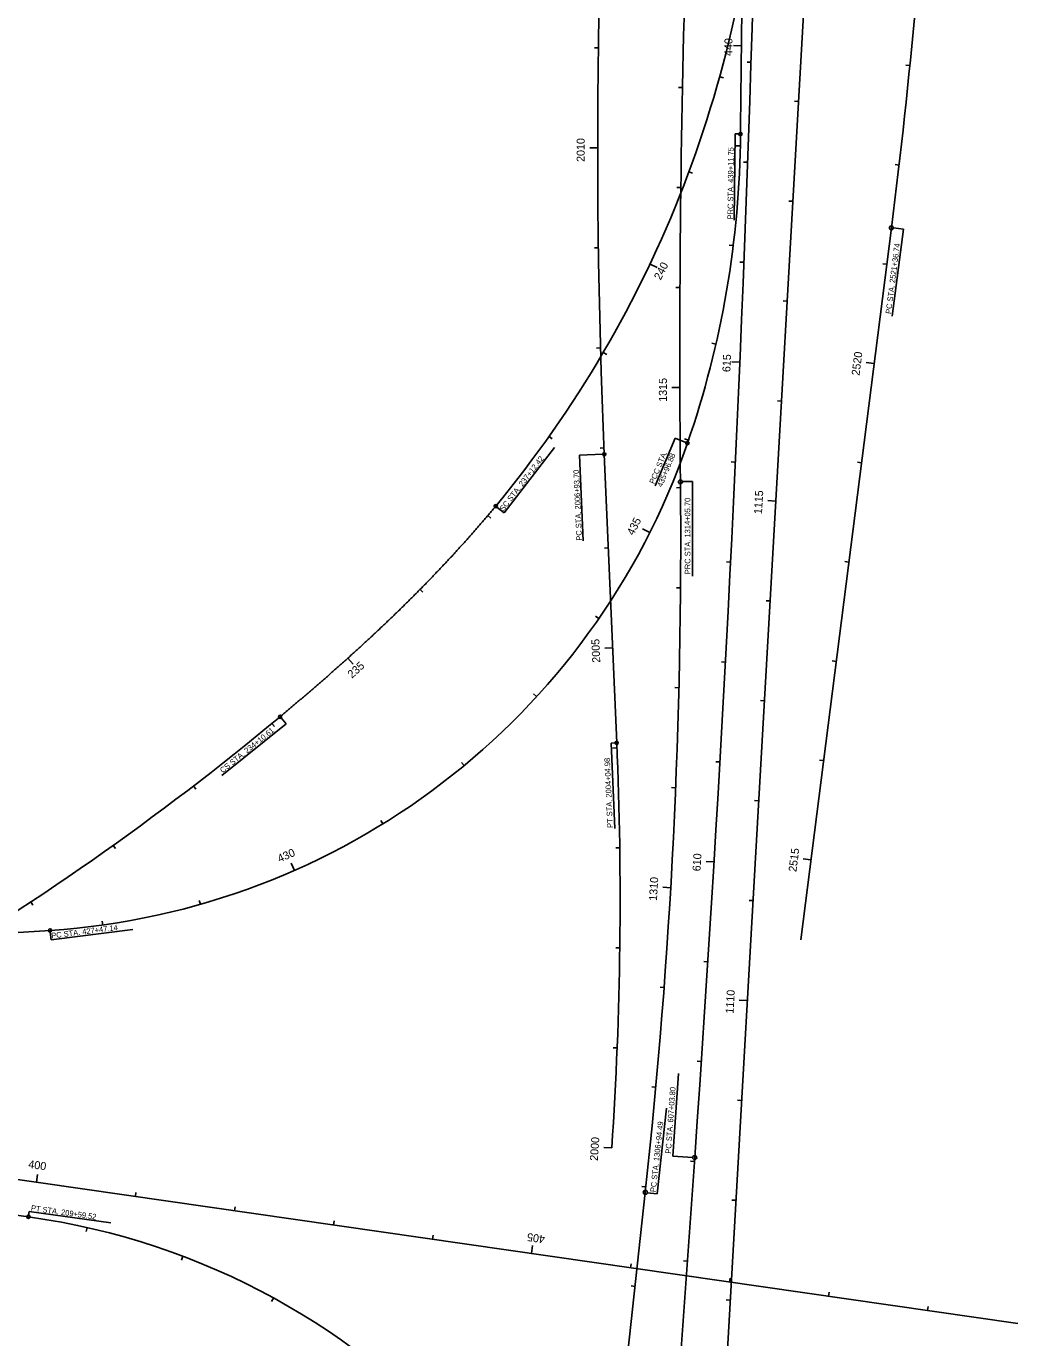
# Model space of a CAD drawing. Extents: x 919451 to 931682, y 583214 to 665619.
# Drawn here: x 928368 to 929359, y 636371 to 637681 of the extents above; entities that cross this region are included whole.
import ezdxf

# ---------------------------------------------------------------- set-up
doc = ezdxf.new("R2010")
doc.units = 0
for name, color, linetype in [('CLConst_dp', 7, 'Continuous'), ('ScratchEle_dp', 7, 'Continuous'), ('StationTicL_dp', 7, 'Continuous'), ('StationTicS_dp', 7, 'Continuous'), ('TextBLStation', 7, 'Continuous')]:
    doc.layers.add(name, color=color, linetype=linetype)

msp = doc.modelspace()

# ---------------------------------------------------------------- linework, layer by layer
at = {"layer": 'CLConst_dp'}
for p, q in [((929063.9, 636273.8), (929152.4, 637830.3)), ((929142.1, 636768.3), (929232.6, 637479.9)), ((928958, 636965.2), (928945.6, 637253.6)), ((928167.9, 636762.9), (928391.5, 636777.8)), ((928999.4, 636034.3), (929036, 636550.8)), ((928273.3, 636541.2), (929359, 636385)), ((928369.9, 636491.6), (928167.4, 636519.8)), ((928945.9, 636143.3), (928986.6, 636516))]:
    msp.add_line(p, q, dxfattribs=at)
for centre, radius, start, end in [((900459.4, 638571.4), 28647.9, 355.95543, 0.62237), ((923173.3, 638251.1), 6108.2, 352.74679, 1.18191), ((942221.1, 637355.5), 13200, 175.79449, 180.5625), ((936146.5, 637562.5), 7207.5, 175.47906, 182.45629), ((942580.8, 637470.1), 13499.5, 177.57389, 179.56031), ((927949.6, 637937.8), 1152.9, 320.3284, 357.4164), ((928111.8, 637581.1), 970, 340.9617, 359.5603), ((928343.4, 637501.2), 725, 273.8083, 340.9617), ((923022, 637167.1), 6000, 353.771, 0.5625), ((926819.4, 639157.2), 2817.5, 300.159, 309.7602), ((925288.2, 636807.8), 3673.2, 356.1393, 2.4563), ((928271, 635782.2), 716.2, 0.0622, 82.0601)]:
    msp.add_arc(centre, radius, start, end, dxfattribs=at)
msp.add_spline([(928621.4, 636991.3), (928624.5, 636993.9), (928627.7, 636996.5), (928630.8, 636999.2), (928633.9, 637001.8), (928637, 637004.4), (928640.1, 637007.1), (928643.2, 637009.7), (928646.3, 637012.3), (928649.4, 637015), (928652.5, 637017.6), (928655.6, 637020.3), (928658.7, 637023), (928661.8, 637025.6), (928664.9, 637028.3), (928668, 637031), (928671, 637033.7), (928674.1, 637036.4), (928677.1, 637039.1), (928680.2, 637041.8), (928683.2, 637044.5), (928686.3, 637047.2), (928689.3, 637049.9), (928692.3, 637052.7), (928695.4, 637055.4), (928698.4, 637058.2), (928701.4, 637060.9), (928704.4, 637063.7), (928707.4, 637066.4), (928710.4, 637069.2), (928713.4, 637072), (928716.4, 637074.8), (928719.3, 637077.6), (928722.3, 637080.4), (928725.3, 637083.2), (928728.2, 637086), (928731.2, 637088.8), (928734.1, 637091.6), (928737, 637094.4), (928740, 637097.3), (928742.9, 637100.1), (928745.8, 637103), (928748.7, 637105.9), (928751.6, 637108.7), (928754.5, 637111.6), (928757.4, 637114.5), (928760.2, 637117.4), (928763.1, 637120.3), (928766, 637123.2), (928768.8, 637126.1), (928771.7, 637129), (928774.5, 637132), (928777.3, 637134.9), (928780.1, 637137.9), (928782.9, 637140.8), (928785.7, 637143.8), (928788.5, 637146.8), (928791.3, 637149.8), (928794.1, 637152.7), (928796.8, 637155.8), (928799.6, 637158.8), (928802.3, 637161.8), (928805.1, 637164.8), (928807.8, 637167.8), (928810.5, 637170.9), (928813.2, 637173.9), (928815.9, 637177), (928818.6, 637180.1), (928821.2, 637183.2), (928823.9, 637186.2), (928826.6, 637189.3), (928829.2, 637192.4), (928831.8, 637195.6), (928834.5, 637198.7), (928837.1, 637201.8)], degree=3, dxfattribs=at)
at = {"layer": 'StationTicL_dp'}
for p, q in [((929075.3, 637487.5), (929076.3, 637573.7)), ((929080.1, 637573.7), (929076.3, 637573.7)), ((929233.5, 637391.6), (929244.6, 637478.6)), ((929244.6, 637478.6), (929234.6, 637479.9)), ((928996.6, 637222.1), (929016.3, 637269.8)), ((929027.2, 637265.3), (929016.3, 637269.8)), ((928895.7, 637260.5), (928845.6, 637195.1)), ((928944, 637253.6), (928920.9, 637252.6)), ((928924.6, 637167.1), (928920.9, 637252.6)), ((929033.7, 637226.3), (929023.7, 637226.3)), ((929033.8, 637131.7), (929033.7, 637226.3)), ((928838.3, 637200.8), (928845.6, 637195.1)), ((928627.4, 636984.2), (928563.3, 636932.5)), ((928622.5, 636990.2), (928627.4, 636984.2)), ((928956.4, 636965.2), (928952.4, 636965)), ((928956, 636879.5), (928952.4, 636965)), ((928391.5, 636776.2), (928392.5, 636768.5)), ((928474.1, 636778.7), (928392.5, 636768.5)), ((929014, 636552.3), (929019.9, 636634.9)), ((928998.5, 636514.6), (929007.8, 636600.2)), ((929034, 636550.9), (929014, 636552.3)), ((928998.5, 636514.6), (928988.6, 636515.7)), ((928370.6, 636497), (928370, 636493.2)), ((928370.6, 636497), (928452.3, 636485.6))]:
    msp.add_line(p, q, dxfattribs=at)
for centre, radius in [((929081.7, 637573.6), 1.6), ((929232.6, 637479.9), 2), ((928945.6, 637253.6), 1.6), ((929028.7, 637264.7), 1.6), ((929021.7, 637226), 2), ((928837.1, 637201.8), 1.6), ((928621.4, 636991.3), 1.6), ((928958, 636965.2), 1.6), ((928391.5, 636777.8), 1.6), ((929036, 636550.8), 2), ((928986.6, 636516), 2), ((928369.9, 636491.6), 1.6)]:
    msp.add_circle(centre, radius, dxfattribs=at)
at = {"layer": 'StationTicS_dp'}
for p, q in [((929082.7, 637661.9), (929074.7, 637662)), ((928939, 637559.8), (928931, 637559.8)), ((928991.3, 637443.7), (928998.5, 637440.2)), ((929081.1, 637345.7), (929073.1, 637346)), ((929215.4, 637344.3), (929207.4, 637345.3)), ((929021.1, 637320.3), (929013.1, 637320.2)), ((929116.9, 637206.9), (929109, 637207.4)), ((928991.1, 637175.5), (928983.9, 637179.1)), ((928953.9, 637060.1), (928946, 637059.8)), ((928689.1, 637049.7), (928694.4, 637043.8)), ((929152.2, 636848.3), (929144.3, 636849.3)), ((928635.8, 636837.8), (928632.6, 636845.1)), ((929055.3, 636846.3), (929047.3, 636846.8)), ((929012, 636820.5), (929004, 636820.9)), ((929088.6, 636707.7), (929080.6, 636708.2)), ((928953.1, 636560.4), (928945.1, 636561)), ((928377.9, 636526.1), (928379, 636534)), ((928872.8, 636454.9), (928873.9, 636462.8))]:
    msp.add_line(p, q, dxfattribs=at)
at = {"layer": 'TextBLStation'}
for p, q in [((928939.7, 637659.8), (928935.7, 637659.9)), ((929092.3, 637645.5), (929088.4, 637645.6)), ((929251.1, 637642.1), (929247.1, 637642.5)), ((929061, 637630.9), (929064.8, 637629.8)), ((929023.7, 637620.2), (929019.7, 637620.3)), ((929139.6, 637606.3), (929135.7, 637606.5)), ((929081.6, 637561.9), (929077.6, 637562)), ((929088.9, 637545.5), (929084.9, 637545.7)), ((929240.3, 637542.7), (929236.3, 637543.2)), ((929030.2, 637535.8), (929033.9, 637534.4)), ((929022.1, 637520.3), (929018.1, 637520.3)), ((929134, 637506.5), (929130, 637506.7)), ((928939.8, 637459.8), (928935.8, 637459.8)), ((929074.4, 637462.2), (929070.5, 637462.7)), ((929085.2, 637445.6), (929081.2, 637445.7)), ((929228, 637443.5), (929224, 637444)), ((929021.2, 637420.3), (929017.2, 637420.3)), ((929128.3, 637406.6), (929124.3, 637406.8)), ((928941.9, 637359.9), (928937.9, 637359.8)), ((929057.1, 637363.8), (929053.2, 637364.7)), ((928944.6, 637355.3), (928948, 637353.3)), ((929122.6, 637306.8), (929118.6, 637307)), ((928890.4, 637271.3), (928893.6, 637269)), ((929029.7, 637267.6), (929025.9, 637268.9)), ((928945.4, 637259.9), (928941.4, 637259.8)), ((929076.6, 637245.8), (929072.6, 637246)), ((929202.7, 637245.1), (929198.8, 637245.6)), ((929021.8, 637220.3), (929017.8, 637220.2)), ((928829.1, 637192.3), (928832.1, 637189.7)), ((928949.7, 637160), (928945.7, 637159.9)), ((929071.8, 637145.9), (929067.8, 637146.1)), ((929190.1, 637145.9), (929186.2, 637146.4)), ((928761.5, 637118.6), (928764.3, 637115.8)), ((929021.8, 637120.3), (929017.8, 637120.3)), ((929111.3, 637107.1), (929107.3, 637107.3)), ((928940.2, 637089.5), (928936.9, 637091.8)), ((929066.7, 637046), (929062.7, 637046.2)), ((929177.5, 637046.7), (929173.5, 637047.2)), ((929020.2, 637020.3), (929016.2, 637020.4)), ((928877.9, 637011.4), (928874.9, 637014.1)), ((929105.6, 637007.3), (929101.6, 637007.5)), ((928613.2, 636984.5), (928615.8, 636981.5)), ((928958.2, 636960.2), (928954.2, 636960)), ((928805.5, 636942.5), (928802.9, 636945.6)), ((929061.2, 636946.2), (929057.2, 636946.4)), ((929164.9, 636947.5), (929160.9, 636948)), ((928535, 636922.3), (928537.4, 636919.1)), ((929016.9, 636920.3), (929012.9, 636920.5)), ((929099.9, 636907.4), (929095.9, 636907.6)), ((928724.3, 636884.3), (928722.2, 636887.7)), ((928454.6, 636862.8), (928456.9, 636859.5)), ((928961, 636860.2), (928957, 636860.2)), ((928372.2, 636806.2), (928374.4, 636802.9)), ((928541.8, 636803.9), (928540.7, 636807.7)), ((929094.2, 636807.6), (929090.3, 636807.8)), ((928444.1, 636783.2), (928443.5, 636787.2)), ((928961.1, 636760.3), (928957.1, 636760.3)), ((929049.1, 636746.5), (929045.1, 636746.8)), ((929005.4, 636720.7), (929001.4, 636721)), ((928958.4, 636660.3), (928954.4, 636660.5)), ((929042.6, 636646.7), (929038.6, 636647)), ((928997.1, 636621), (928993.1, 636621.4)), ((929082.9, 636607.9), (929078.9, 636608.1)), ((929035.7, 636547), (929031.7, 636547.3)), ((928987.2, 636521.5), (928983.2, 636521.9)), ((928476.8, 636511.9), (928477.4, 636515.8)), ((929077.2, 636508.1), (929073.2, 636508.3)), ((928575.8, 636497.6), (928576.4, 636501.6)), ((928428.5, 636480.9), (928427.6, 636477)), ((928674.8, 636483.4), (928675.4, 636487.4)), ((928773.8, 636469.2), (928774.4, 636473.1)), ((928524.2, 636452.2), (928522.8, 636448.4)), ((928971.8, 636440.7), (928972.3, 636444.6)), ((929028.6, 636447.2), (929024.7, 636447.5)), ((929070.7, 636426.4), (929071.3, 636430.4)), ((928976.3, 636422.1), (928972.4, 636422.5)), ((929169.7, 636412.2), (929170.3, 636416.2)), ((928614.9, 636410.4), (928613, 636406.9)), ((929071.5, 636408.2), (929067.6, 636408.5)), ((929268.7, 636398), (929269.3, 636401.9))]:
    msp.add_line(p, q, dxfattribs=at)

# ---------------------------------------------------------------- texts
at = {"layer": 'ScratchEle_dp'}
for s, rotation, p in [('440', 89.1857, (929073.5, 637651.6)), ('2010', 90.0214, (928926, 637545.8)), ('240', 63.1235, (929001.9, 637427.1)), ('615', 87.5478, (929071.6, 637335.6)), ('2520', 82.7468, (929200.7, 637332)), ('1315', 90.1532, (929008.2, 637306.1)), ('1115', 86.7468, (929103.2, 637193.6)), ('435', 63.3057, (928974.8, 637171.9)), ('2005', 92.4563, (928941.6, 637045.5)), ('235', 41.9666, (928693.3, 637029.3)), ('430', 23.7914, (928621, 636845.5)), ('610', 86.5478, (929041.7, 636836.7)), ('2515', 82.7468, (929137.6, 636835.9)), ('1310', 86.6884, (928998.2, 636807.2)), ('1110', 86.7468, (929074.8, 636694.5)), ('2000', 86.1393, (928939.1, 636547.3)), ('400', 351.813, (928369.4, 636540.5)), ('405', 171.813, (928886.7, 636472.9))]:
    msp.add_text(s, height=8, rotation=rotation, dxfattribs=at).set_placement(p)
at = {"layer": 'StationTicL_dp'}
for s, rotation, p in [('PRC STA. 439+11.75', 89.373, (929074.3, 637488.3)), ('PC STA. 2521+36.74', 82.7468, (929232.3, 637393.6)), ('PCC STA.', 67.5991, (928995.5, 637223.5)), ('435+96.88', 67.5991, (929003.3, 637220.3)), ('SC STA. 237+12.42', 52.5045, (928844.9, 637196.2)), ('PC STA. 2006+93.70', 92.4563, (928923.3, 637167.4)), ('PRC STA. 1314+05.70', 90.0578, (929031.7, 637133.8)), ('CS STA. 234+10.61', 38.9186, (928564.1, 636934.7)), ('PT STA. 2004+04.98', 92.4563, (928954.2, 636880.3)), ('PC STA. 427+47.14', 7.1324, (928393.1, 636769.7)), ('PC STA. 607+03.80', 85.9554, (929012.2, 636554.5)), ('PC STA. 1306+94.49', 83.771, (928997, 636516)), ('PT STA. 209+59.52', 352.0601, (928372.1, 636497.8))]:
    msp.add_text(s, height=5.6, rotation=rotation, dxfattribs=at).set_placement(p)

doc.saveas('drawing.dxf')
